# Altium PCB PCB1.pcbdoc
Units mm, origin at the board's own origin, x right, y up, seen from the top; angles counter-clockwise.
Board outline 203.2 x 30.23 mm, 2 copper layers (Top Layer, Bottom Layer); 0 components, 0 nets, 22 pads, 0 vias.
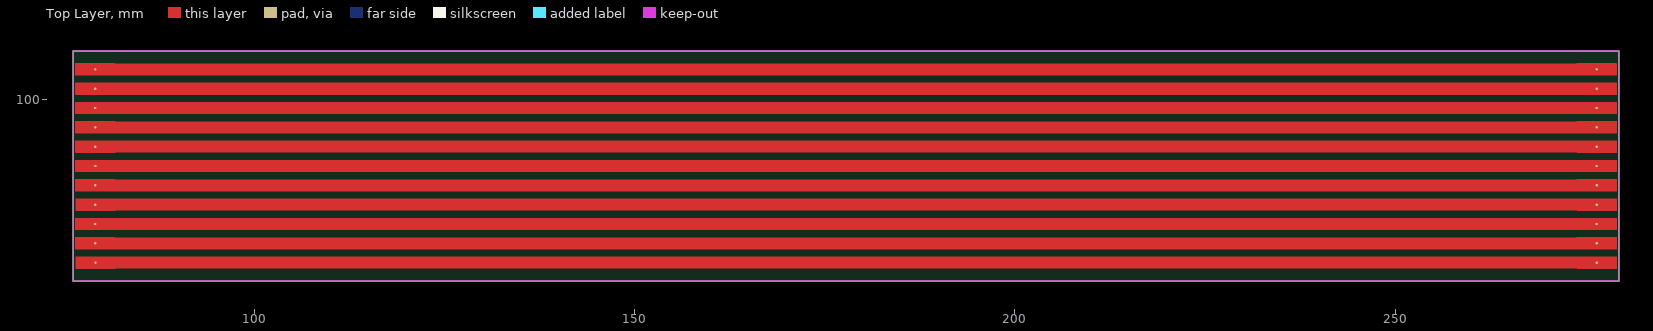
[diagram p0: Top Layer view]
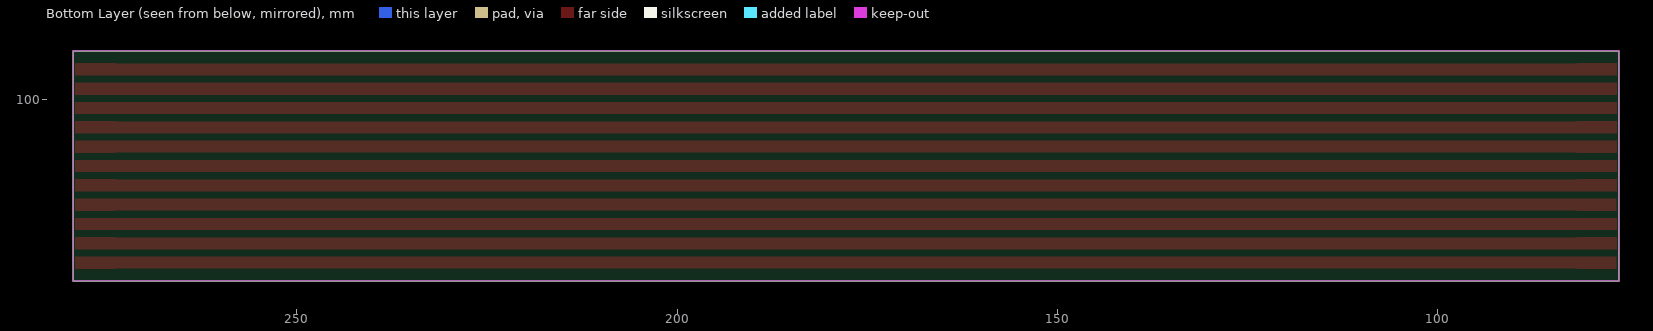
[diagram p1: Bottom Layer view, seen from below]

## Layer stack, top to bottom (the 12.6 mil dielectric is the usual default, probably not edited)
Top Layer: signal copper (thickness not stored)
Dielectric: dielectric 0.32, FR-4, Dk 4.8
Bottom Layer: signal copper (thickness not stored)

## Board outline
76.2,106.426 279.4,106.426 279.4,76.2 76.2,76.2

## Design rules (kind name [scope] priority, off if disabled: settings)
BoardOutlineClearance copperThickness1oz [All] p0: genericclearance=0.254 ignorepadtopadclearanceinfootprint=FALSE except(0: Arc-SplitContinuation Track-SplitContinuation SMDPad-SplitContinuation THPad-SplitContinuation Via-SplitContinuation Fill-SplitContinuation Poly-SplitContinuation Region-SplitContinuation Text-SplitContinuation; 0.152: Track-CutoutEdge SMDPad-CutoutEdge THPad-CutoutEdge Via-CutoutEdge Region-CutoutEdge; 0.3: Track-OutlineEdge SMDPad-OutlineEdge THPad-OutlineEdge Via-OutlineEdge Fill-OutlineEdge Region-OutlineEdge Poly-OutlineEdge Text-OutlineEdge Fill-CutoutEdge)
BoardOutlineClearance copperThickness2oz [All] p0: genericclearance=0.254 ignorepadtopadclearanceinfootprint=FALSE except(0: Arc-SplitContinuation Track-SplitContinuation SMDPad-SplitContinuation THPad-SplitContinuation Via-SplitContinuation Fill-SplitContinuation Poly-SplitContinuation Region-SplitContinuation Text-SplitContinuation; 0.152: Track-CutoutEdge SMDPad-CutoutEdge THPad-CutoutEdge Via-CutoutEdge Region-CutoutEdge; 0.3: Track-OutlineEdge SMDPad-OutlineEdge THPad-OutlineEdge Via-OutlineEdge Fill-OutlineEdge Region-OutlineEdge Poly-OutlineEdge Text-OutlineEdge Fill-CutoutEdge)
Clearance copperThickness1oz [All] p1: gap=0.178 ignorepadtopadclearanceinfootprint=FALSE except(0.102: Track-Track; 0.152: Track-SMDPad SMDPad-SMDPad Track-THPad SMDPad-THPad THPad-THPad Track-Via SMDPad-Via THPad-Via Via-Via SMDPad-Fill THPad-Fill Via-Fill Fill-Fill Track-Region SMDPad-Region THPad-Region Via-Region Region-Region Track-Poly SMDPad-Poly THPad-Poly Via-Poly Fill-Poly Region-Poly Poly-Poly Track-Text SMDPad-Text THPad-Text Via-Text Fill-Text Region-Text Poly-Text Text-Text; 0.175: Track-Hole SMDPad-Hole THPad-Hole Via-Hole Fill-Hole Region-Hole Poly-Hole Text-Hole Sheet-Hole; 0.3: Track-Fill Fill-Region Track-Sheet SMDPad-Sheet THPad-Sheet Via-Sheet Fill-Sheet Region-Sheet Poly-Sheet Text-Sheet)
Clearance copperThickness2oz [All] p1: gap=0.178 ignorepadtopadclearanceinfootprint=FALSE except(0.152: Track-SMDPad SMDPad-SMDPad Track-THPad SMDPad-THPad THPad-THPad Track-Via SMDPad-Via THPad-Via Via-Via SMDPad-Fill THPad-Fill Via-Fill Fill-Fill Track-Region SMDPad-Region THPad-Region Via-Region Region-Region Track-Poly SMDPad-Poly THPad-Poly Via-Poly Fill-Poly Region-Poly Poly-Poly Track-Text SMDPad-Text THPad-Text Via-Text Fill-Text Region-Text Poly-Text Text-Text; 0.175: Track-Hole SMDPad-Hole THPad-Hole Via-Hole Fill-Hole Region-Hole Poly-Hole Text-Hole Sheet-Hole; 0.203: Track-Track; 0.3: Track-Fill Fill-Region Track-Sheet SMDPad-Sheet THPad-Sheet Via-Sheet Fill-Sheet Region-Sheet Poly-Sheet Text-Sheet)
DiffPairsRouting differentialPair [All] p1: maxuncoupledlength=10 minlimit=6 maxlimit=6 mostfreqgap=6 toplayer_minwidth=5 toplayer_prefwidth=10 toplayer_maxwidth=100 bottomlayer_minwidth=5 bottomlayer_prefwidth=10 bottomlayer_maxwidth=100
PasteMaskExpansion pasteMaskExpansion [All] p1: expansion=0
PlaneConnect innerPlane [All] p1: planeconnectstyle=Relief reliefexpansion=0.508 reliefentries=4 reliefconductorwidth=0.254 reliefairgap=0.254
PolygonConnect copperRegion [All] p1: connectstyle=Relief reliefentries=4 reliefconductorwidth=10 polygonreliefangle="90 Angle" airgapwidth=10
RoutingVias viaSize [All] p1: viastyle="Through Hole" holewidth=12.0078 minholewidth=11.811 maxholewidth=248.0314 width=24.0158 minwidth=19.685 maxwidth=393.7008
SolderMaskExpansion solderMaskExpansion [All] p1: useseparateexpansions=TRUE expansion=2 expansionbottom=2
Width copperThickness1oz [All] p1: maxlimit=100 minlimit=5 preferedwidth=5
Width copperThickness2oz [All] p1: maxlimit=100 minlimit=8 preferedwidth=10

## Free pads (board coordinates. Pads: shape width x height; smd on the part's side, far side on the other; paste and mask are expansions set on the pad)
  round 0.312 smd: 1(79.109,81.153) 1(79.109,83.693) 1(79.109,88.773) 1(79.109,98.933) 1(79.109,101.473) 1(79.109,104.013) 1(79.121,91.313) 1(79.121,93.853) 1(79.121,96.393) 1(79.131,86.233) 1(79.153,78.613) 1(276.479,78.613) 1(276.479,81.153) 1(276.479,83.693) 1(276.479,86.233) 1(276.479,88.773) 1(276.479,91.313) 1(276.479,93.853) 1(276.479,96.393) 1(276.479,98.933) 1(276.479,101.473) 1(276.479,104.013)

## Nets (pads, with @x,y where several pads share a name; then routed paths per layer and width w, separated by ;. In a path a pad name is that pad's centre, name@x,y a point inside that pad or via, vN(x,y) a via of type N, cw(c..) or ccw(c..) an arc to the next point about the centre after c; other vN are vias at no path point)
copper on no net: | length 2210.2
  Top Layer w1.587: 77.295,104.013 278.237,104.013 ; 77.3,101.473 278.217,101.473 ; 77.308,83.693 278.237,83.693 ; 77.313,96.393 278.247,96.393 ; 77.317,93.853 278.267,93.853 ; 77.317,98.933 278.247,98.933 ; 77.326,88.773 278.227,88.773 ; 77.33,81.153 278.267,81.153 ; 77.33,86.233 278.247,86.233 ; 77.33,91.313 278.247,91.313 ; 77.334,78.613 278.237,78.613

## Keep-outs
Board Outline Layer:
  the board outline again, w0.254

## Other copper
Top Layer:
  region: 279.082,102.247 279.082,100.693 273.906,100.693 273.875,100.723 273.875,102.253 279.076,102.253
  region: 279.082,104.787 279.082,103.233 273.906,103.233 273.875,103.263 273.875,104.793 279.076,104.793
  region: 279.082,99.707 279.082,98.153 273.906,98.153 273.875,98.183 273.875,99.713 279.076,99.713
  region: 279.082,97.167 279.082,95.613 273.906,95.613 273.875,95.643 273.875,97.173 279.076,97.173
  region: 279.082,94.627 279.082,93.073 273.906,93.073 273.875,93.103 273.875,94.633 279.076,94.633
  region: 279.082,92.087 279.082,90.533 273.906,90.533 273.875,90.563 273.875,92.093 279.076,92.093
  region: 279.082,89.547 279.082,87.993 273.906,87.993 273.875,88.023 273.875,89.553 279.076,89.553
  region: 279.082,87.007 279.082,85.453 273.906,85.453 273.875,85.483 273.875,87.013 279.076,87.013
  region: 279.082,84.467 279.082,82.913 273.906,82.913 273.875,82.943 273.875,84.473 279.076,84.473
  region: 279.082,81.927 279.082,80.373 273.906,80.373 273.875,80.403 273.875,81.933 279.076,81.933
  region: 279.082,79.387 279.082,77.833 273.906,77.833 273.875,77.863 273.875,79.393 279.076,79.393
  region: 81.712,104.787 81.712,103.233 76.536,103.233 76.505,103.263 76.505,104.793 81.706,104.793
  region: 81.712,102.247 81.712,100.693 76.536,100.693 76.505,100.723 76.505,102.253 81.706,102.253
  region: 81.712,99.707 81.712,98.153 76.536,98.153 76.505,98.183 76.505,99.713 81.706,99.713
  region: 81.724,97.167 81.724,95.613 76.548,95.613 76.517,95.643 76.517,97.173 81.718,97.173
  region: 81.724,94.627 81.724,93.073 76.548,93.073 76.517,93.103 76.517,94.633 81.718,94.633
  region: 81.724,92.087 81.724,90.533 76.548,90.533 76.517,90.563 76.517,92.093 81.718,92.093
  region: 81.712,89.547 81.712,87.993 76.536,87.993 76.505,88.023 76.505,89.553 81.706,89.553
  region: 81.735,87.007 81.735,85.453 76.558,85.453 76.528,85.483 76.528,87.013 81.728,87.013
  region: 81.712,84.467 81.712,82.913 76.536,82.913 76.505,82.943 76.505,84.473 81.706,84.473
  region: 81.712,81.927 81.712,80.373 76.536,80.373 76.505,80.403 76.505,81.933 81.706,81.933
  region: 81.757,79.387 81.757,77.833 76.58,77.833 76.55,77.863 76.55,79.393 81.75,79.393

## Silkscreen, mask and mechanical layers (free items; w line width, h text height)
Mech3:
  region: 253.746,106.172 279.146,106.172 279.146,76.454 253.746,76.454
  region: 76.359,106.172 101.759,106.172 101.759,76.454 76.359,76.454
  region: 103.759,101.981 252.095,101.981 252.095,98.552 103.759,98.552
  region: 103.378,84.138 251.714,84.138 251.714,80.709 103.378,80.709
  region: 103.621,93.027 251.957,93.027 251.957,89.599 103.621,89.599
